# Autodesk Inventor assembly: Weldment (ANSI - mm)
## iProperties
Length Units: 11269
Angle Units: 11283
Time Units: 11279
Mass Units: 11290
Length Display Precision: 3
Angle Display Precision: 2
Part Number: Weldment (ANSI - mm)
Document SubType Name: Weldment
Created: 2002-06
Designer: smithga
Part Number: chapter 8
Created: 2002-11
Designer: Elise Moss
Control State: 0
Master: False
Shininess: 64.0
Angle Units: 11279
Time Units: 11290
Mass Units: 11283
Compacted: True
Density: 0.0
Volumn: 0.0
Area: 0.0
PropertySet Name: Model Information
Author: Elise Moss
